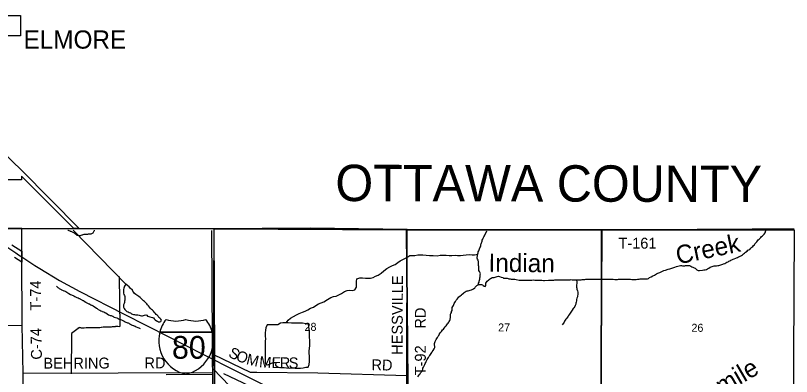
# Model space of a CAD drawing. Extents: x 1588073 to 2013523, y 1090242 to 1357120.
# Drawn here: x 1754621 to 1775971, y 1256594 to 1266514 of the extents above; entities that cross this region are included whole.
import ezdxf

# ---------------------------------------------------------------- set-up
doc = ezdxf.new("R2010")
doc.units = 0
for name, color, linetype in [('GM_X_Adjacent_County', 7, 'Continuous'), ('GM_X_Adjacent_County_Text', 7, 'Continuous'), ('GM_X_Corporation', 7, 'Continuous'), ('GM_X_Corporation_Text', 7, 'Continuous'), ('GM_X_County', 7, 'Continuous'), ('GM_X_County_Road', 7, 'Continuous'), ('GM_X_County_Road_Text', 7, 'Continuous'), ('GM_X_Interstate_Location', 7, 'Continuous'), ('GM_X_Interstate_Route', 7, 'Continuous'), ('GM_X_Interstate_Shield', 7, 'Continuous'), ('GM_X_Minor_Lake', 7, 'Continuous'), ('GM_X_Minor_River', 7, 'Continuous'), ('GM_X_Minor_River_Text', 7, 'Continuous'), ('GM_X_Section', 7, 'Continuous'), ('GM_X_Section_Text', 7, 'Continuous'), ('GM_X_State_Route', 7, 'Continuous'), ('GM_X_Township', 7, 'Continuous'), ('GM_X_Township_Road', 7, 'Continuous'), ('GM_X_Township_Road_Text', 7, 'Continuous')]:
    doc.layers.add(name, color=color, linetype=linetype)

msp = doc.modelspace()

# ---------------------------------------------------------------- linework, layer by layer
at = {"layer": 'GM_X_Adjacent_County'}
msp.add_lwpolyline([(1753720, 1260662), (1754797, 1260665), (1760083, 1260656), (1762727, 1260673), (1765400, 1260637), (1770764, 1260628), (1770979, 1260628), (1771265, 1260627), (1771684, 1260628), (1772128, 1260628), (1772506, 1260627), (1773015, 1260628), (1773375, 1260630), (1773589, 1260631), (1773829, 1260633), (1774262, 1260637), (1774492, 1260637), (1774886, 1260638), (1775116, 1260640), (1775856, 1260641), (1776044, 1260641)], dxfattribs=at)
at = {"layer": 'GM_X_Corporation'}
for points in [[(1753089, 1266514), (1754756, 1266514), (1754759, 1266288), (1754760, 1266162), (1754759, 1266044), (1754757, 1265960), (1754718, 1265961), (1754408, 1265960)], [(1753756, 1263240), (1754783, 1262263), (1756374, 1260663), (1756225, 1260662), (1754784, 1262101), (1754785, 1261998), (1753120, 1261998)], [(1754523, 1260215), (1754793, 1260039), (1754791, 1259878), (1754791, 1259736), (1754595, 1259865)]]:
    msp.add_lwpolyline(points, dxfattribs=at)
at = {"layer": 'GM_X_County'}
msp.add_lwpolyline([(1753720, 1260662), (1754797, 1260665), (1760083, 1260656), (1762727, 1260673), (1765400, 1260637), (1770764, 1260628), (1770979, 1260628), (1771265, 1260627), (1771684, 1260628), (1772128, 1260628), (1772506, 1260627), (1773015, 1260628), (1773375, 1260630), (1773589, 1260631), (1773829, 1260633), (1774262, 1260637), (1774492, 1260637), (1774886, 1260638), (1775116, 1260640), (1775856, 1260641), (1776044, 1260641)], dxfattribs=at)
at = {"layer": 'GM_X_County_Road'}
for points in [[(1760069, 1257196), (1760083, 1260656)], [(1752156, 1257998), (1754803, 1258006)], [(1754829, 1256687), (1754803, 1258006)], [(1759946, 1242582), (1760099, 1247215), (1760179, 1250093), (1760141, 1250222), (1760108, 1252739), (1760060, 1256704), (1760069, 1257059), (1760069, 1257196)], [(1760069, 1257196), (1761079, 1256712), (1761261, 1256710), (1761263, 1256710)], [(1754829, 1256687), (1760060, 1256704)], [(1761263, 1256710), (1762943, 1256691), (1765384, 1256619)], [(1765398, 1255365), (1765384, 1256619)]]:
    msp.add_lwpolyline(points, dxfattribs=at)
at = {"layer": 'GM_X_Interstate_Route'}
for points in [[(1753606, 1260661), (1753766, 1260560), (1754626, 1259989), (1754703, 1259938)], [(1754703, 1259938), (1754791, 1259878), (1755155, 1259642), (1755289, 1259557), (1755835, 1259231), (1756392, 1258927), (1757613, 1258305), (1758839, 1257685), (1759779, 1257207), (1760069, 1257059), (1760393, 1256899), (1761194, 1256491), (1762560, 1255798), (1762986, 1255590), (1763226, 1255479), (1763954, 1255170), (1764295, 1255029), (1765404, 1254577), (1765567, 1254515), (1766890, 1253983), (1769289, 1253012), (1770022, 1252715), (1770708, 1252436)]]:
    msp.add_lwpolyline(points, dxfattribs=at)
at = {"layer": 'GM_X_Interstate_Shield'}
for p, q in [((1758588, 1257808), (1760031, 1257808)), ((1760031, 1257808), (1758588, 1257808)), ((1760031, 1257808), (1758588, 1257808))]:
    msp.add_line(p, q, dxfattribs=at)
for centre, start, end in [((1759497, 1257578), 141.669, 165.8066), ((1759036, 1259056), 253.0091, 286.9909), ((1759584, 1259056), 253.0091, 286.9909), ((1759122, 1257578), 14.1934, 38.331), ((1759497, 1257578), 165.8066, 258.463), ((1759122, 1257578), 281.537, 14.1934)]:
    msp.add_arc(centre, 938, start, end, dxfattribs=at)
at = {"layer": 'GM_X_Minor_Lake'}
for p, q in [((1762712, 1257817), (1762686, 1258028)), ((1762716, 1257438), (1762712, 1257817))]:
    msp.add_line(p, q, dxfattribs=at)
for points in [[(1757656, 1259131), (1757641, 1259105), (1757623, 1259075), (1757612, 1259047), (1757598, 1259020), (1757589, 1258982), (1757591, 1258944), (1757596, 1258911), (1757594, 1258881), (1757603, 1258849), (1757615, 1258821), (1757624, 1258787), (1757632, 1258753), (1757633, 1258723), (1757633, 1258694), (1757623, 1258663), (1757616, 1258631), (1757608, 1258599), (1757595, 1258565), (1757591, 1258533), (1757596, 1258499), (1757608, 1258466), (1757629, 1258436), (1757657, 1258406), (1757688, 1258381), (1757716, 1258367), (1757748, 1258356), (1757780, 1258340), (1757810, 1258315), (1757837, 1258307), (1757865, 1258298), (1757895, 1258294), (1757925, 1258291), (1757955, 1258285), (1757983, 1258284), (1758019, 1258274), (1758053, 1258265), (1758085, 1258259), (1758113, 1258258), (1758145, 1258266), (1758173, 1258278), (1758204, 1258287), (1758236, 1258281), (1758255, 1258252), (1758287, 1258238), (1758315, 1258233), (1758357, 1258221), (1758389, 1258216), (1758417, 1258206), (1758436, 1258176), (1758466, 1258149), (1758502, 1258125), (1758529, 1258110), (1758559, 1258096), (1758589, 1258093), (1758621, 1258107), (1758636, 1258137), (1758618, 1258165), (1758595, 1258193), (1758565, 1258216), (1758543, 1258248), (1758518, 1258279), (1758490, 1258299), (1758463, 1258330), (1758439, 1258358), (1758417, 1258390), (1758390, 1258417), (1758360, 1258433), (1758336, 1258462), (1758309, 1258494), (1758281, 1258531), (1758256, 1258559), (1758230, 1258591), (1758173, 1258650), (1758143, 1258673), (1758112, 1258703), (1758082, 1258736), (1758049, 1258762), (1758017, 1258787), (1757985, 1258810), (1757957, 1258830), (1757928, 1258850), (1757898, 1258877), (1757874, 1258905), (1757851, 1258936), (1757835, 1258964), (1757776, 1259025), (1757750, 1259055)], [(1757750, 1259055), (1757656, 1259131)], [(1762686, 1258028), (1762616, 1258036), (1762518, 1258055), (1762365, 1258056), (1762291, 1258060), (1762215, 1258063), (1762127, 1258069), (1762059, 1258072), (1761977, 1258070), (1761909, 1258059), (1761840, 1258011), (1761772, 1258011), (1761696, 1258016), (1761620, 1258012), (1761548, 1258015), (1761506, 1257933), (1761495, 1257865), (1761487, 1257796), (1761494, 1257702), (1761495, 1257628), (1761493, 1257560), (1761488, 1257479), (1761486, 1257391), (1761489, 1257315), (1761493, 1257233), (1761492, 1257154), (1761488, 1257072), (1761487, 1257004), (1761495, 1256934), (1761567, 1256915), (1761641, 1256949), (1761711, 1256981), (1761783, 1256974), (1761773, 1256906), (1761847, 1256849), (1761935, 1256841), (1762013, 1256836), (1762081, 1256832), (1762149, 1256825), (1762231, 1256827), (1762317, 1256826), (1762387, 1256824), (1762461, 1256825), (1762535, 1256835), (1762606, 1256847), (1762676, 1256846), (1762704, 1256926), (1762707, 1257006), (1762713, 1257079), (1762706, 1257161), (1762702, 1257229), (1762703, 1257297), (1762716, 1257438)]]:
    msp.add_lwpolyline(points, dxfattribs=at)
at = {"layer": 'GM_X_Minor_River'}
for p, q in [((1756209, 1260617), (1757655, 1259130)), ((1760016, 1260606), (1760042, 1255883)), ((1757470, 1259342), (1757494, 1257969)), ((1756160, 1257778), (1756155, 1256670)), ((1756380, 1257939), (1756160, 1257778)), ((1756160, 1257778), (1756160, 1257778)), ((1756326, 1257926), (1756326, 1257928)), ((1760050, 1256809), (1762754, 1254048)), ((1760342, 1256676), (1762756, 1255544)), ((1760038, 1256649), (1758762, 1256638))]:
    msp.add_line(p, q, dxfattribs=at)
for points in [[(1756059, 1260617), (1756072, 1260613), (1756086, 1260605), (1756113, 1260593), (1756127, 1260588), (1756147, 1260586), (1756165, 1260582), (1756181, 1260572), (1756199, 1260559), (1756213, 1260547), (1756231, 1260539), (1756249, 1260527), (1756262, 1260514), (1756280, 1260502), (1756298, 1260488), (1756312, 1260480), (1756332, 1260473), (1756350, 1260469), (1756368, 1260471), (1756386, 1260468), (1756408, 1260470), (1756430, 1260474), (1756452, 1260483), (1756466, 1260489), (1756486, 1260499), (1756507, 1260501), (1756525, 1260502), (1756539, 1260504), (1756559, 1260506), (1756591, 1260506), (1756611, 1260509), (1756629, 1260511), (1756647, 1260515), (1756663, 1260516), (1756681, 1260516), (1756703, 1260518), (1756719, 1260522), (1756735, 1260531), (1756753, 1260545), (1756770, 1260563), (1756780, 1260577), (1756786, 1260593), (1756790, 1260607), (1756793, 1260613)], [(1766694, 1258596), (1766712, 1258630), (1766723, 1258654), (1766747, 1258690), (1766769, 1258720), (1766801, 1258758), (1766822, 1258782), (1766846, 1258802), (1766892, 1258834), (1766914, 1258856), (1766946, 1258879), (1766967, 1258901), (1766997, 1258921), (1767021, 1258935), (1767049, 1258945), (1767075, 1258949), (1767107, 1258955), (1767131, 1258965), (1767163, 1258972), (1767203, 1258996), (1767226, 1259006), (1767254, 1259026), (1767266, 1259048), (1767290, 1259066), (1767318, 1259090), (1767346, 1259112), (1767361, 1259136), (1767363, 1259158), (1767377, 1259188), (1767381, 1259212), (1767387, 1259240), (1767392, 1259266), (1767400, 1259308), (1767404, 1259336), (1767408, 1259358), (1767408, 1259392), (1767413, 1259414), (1767403, 1259442), (1767383, 1259478), (1767373, 1259505), (1767371, 1259563), (1767370, 1259589), (1767366, 1259617), (1767360, 1259645), (1767358, 1259673), (1767361, 1259725), (1767357, 1259749), (1767349, 1259786), (1767335, 1259816), (1767327, 1259842), (1767327, 1259868), (1767330, 1259910), (1767334, 1259938), (1767340, 1259962), (1767348, 1259996), (1767354, 1260020), (1767365, 1260044), (1767375, 1260072), (1767385, 1260098), (1767395, 1260126), (1767411, 1260160), (1767420, 1260186), (1767428, 1260218), (1767436, 1260242), (1767440, 1260267), (1767450, 1260289), (1767457, 1260315), (1767463, 1260339), (1767479, 1260365), (1767491, 1260393), (1767509, 1260429), (1767526, 1260457), (1767589, 1260600)], [(1774993, 1260271), (1775015, 1260293), (1775036, 1260319), (1775058, 1260345), (1775080, 1260365), (1775106, 1260391), (1775126, 1260415), (1775145, 1260439), (1775173, 1260458), (1775193, 1260480), (1775221, 1260508), (1775247, 1260542), (1775262, 1260605)], [(1771701, 1259263), (1771733, 1259264), (1771777, 1259268), (1771811, 1259274), (1771849, 1259274), (1771879, 1259278), (1771913, 1259277), (1771953, 1259279), (1771981, 1259279), (1772013, 1259281), (1772039, 1259289), (1772061, 1259311), (1772110, 1259334), (1772158, 1259356), (1772200, 1259374), (1772232, 1259394), (1772258, 1259412), (1772294, 1259429), (1772325, 1259441), (1772349, 1259455), (1772371, 1259463), (1772425, 1259487), (1772455, 1259505), (1772509, 1259518), (1772582, 1259546), (1772620, 1259554), (1772650, 1259562), (1772678, 1259567), (1772702, 1259575), (1772760, 1259599), (1772808, 1259619), (1772840, 1259625), (1772883, 1259636), (1772913, 1259640), (1772943, 1259640), (1772969, 1259638), (1772997, 1259638), (1773035, 1259639), (1773057, 1259641), (1773111, 1259645), (1773137, 1259645), (1773161, 1259643), (1773201, 1259626), (1773233, 1259608), (1773255, 1259596), (1773289, 1259584), (1773317, 1259571), (1773352, 1259547), (1773366, 1259525), (1773406, 1259509), (1773442, 1259506), (1773520, 1259516), (1773557, 1259522), (1773595, 1259528), (1773631, 1259531), (1773657, 1259553), (1773699, 1259569), (1773737, 1259597), (1773787, 1259613), (1773820, 1259626), (1773848, 1259630), (1773880, 1259634), (1773904, 1259636), (1773940, 1259640), (1773976, 1259646), (1773998, 1259649), (1774054, 1259669), (1774078, 1259679), (1774104, 1259685), (1774134, 1259703), (1774165, 1259713), (1774191, 1259732), (1774225, 1259746), (1774249, 1259764), (1774271, 1259772), (1774303, 1259788), (1774347, 1259808), (1774370, 1259822), (1774396, 1259829), (1774436, 1259845), (1774462, 1259853), (1774490, 1259865), (1774516, 1259881), (1774538, 1259889), (1774562, 1259901), (1774592, 1259920), (1774627, 1259940), (1774651, 1259962), (1774679, 1259980), (1774707, 1260008), (1774749, 1260040), (1774772, 1260062), (1774796, 1260072), (1774822, 1260086), (1774854, 1260119), (1774884, 1260143), (1774908, 1260167), (1774929, 1260189), (1774951, 1260215), (1774963, 1260237), (1774993, 1260271)], [(1762071, 1258071), (1762120, 1258138), (1762190, 1258193), (1762267, 1258243), (1762349, 1258289), (1762429, 1258322), (1762514, 1258358), (1762586, 1258391), (1762660, 1258427), (1762739, 1258469), (1762815, 1258502), (1762883, 1258544), (1762960, 1258594), (1763030, 1258619), (1763106, 1258645), (1763207, 1258710), (1763297, 1258766), (1763367, 1258790), (1763444, 1258805), (1763516, 1258835), (1763586, 1258873), (1763673, 1258930), (1763747, 1258960), (1763815, 1258963), (1763883, 1258961), (1763953, 1258977), (1764002, 1259048), (1764001, 1259133), (1764001, 1259203), (1764014, 1259275), (1764094, 1259301), (1764164, 1259302), (1764246, 1259300), (1764386, 1259295), (1764460, 1259312), (1764529, 1259354), (1764601, 1259380), (1764677, 1259431), (1764758, 1259499), (1764834, 1259557), (1764923, 1259608), (1764991, 1259640), (1765067, 1259672), (1765138, 1259729), (1765206, 1259771), (1765293, 1259815), (1765385, 1259864), (1765466, 1259916), (1765538, 1259921), (1765606, 1259921), (1765688, 1259933), (1765762, 1259936), (1765832, 1259938), (1765920, 1259931), (1766014, 1259920), (1766114, 1259916), (1766218, 1259913), (1766301, 1259927), (1766369, 1259926), (1766471, 1259924), (1766555, 1259923), (1766627, 1259921), (1766717, 1259924), (1766785, 1259922), (1766861, 1259921), (1766941, 1259929), (1767022, 1259934), (1767108, 1259944), (1767184, 1259937), (1767252, 1259937), (1767339, 1259957)], [(1767355, 1259125), (1767397, 1259121), (1767443, 1259121), (1767467, 1259115), (1767490, 1259091), (1767514, 1259072), (1767542, 1259068), (1767557, 1259096), (1767561, 1259134), (1767565, 1259158), (1767575, 1259184), (1767599, 1259212), (1767640, 1259248), (1767662, 1259264), (1767686, 1259282), (1767710, 1259296), (1767734, 1259310), (1767758, 1259314), (1767790, 1259315), (1767818, 1259321), (1767849, 1259335), (1767873, 1259343), (1767909, 1259347), (1767933, 1259345), (1767983, 1259326), (1768025, 1259310), (1768049, 1259298), (1768085, 1259294), (1768117, 1259297), (1768147, 1259293), (1768173, 1259287), (1768195, 1259281), (1768227, 1259273), (1768259, 1259270), (1768309, 1259270), (1768331, 1259272), (1768359, 1259270), (1768393, 1259255), (1768477, 1259237), (1768519, 1259237), (1768585, 1259240), (1768613, 1259238), (1768651, 1259240), (1768673, 1259242), (1768719, 1259241), (1768745, 1259243), (1768773, 1259243), (1768829, 1259245), (1768869, 1259246), (1768911, 1259244), (1768957, 1259242), (1769005, 1259242), (1769101, 1259237), (1769145, 1259235), (1769175, 1259234), (1769282, 1259236), (1769314, 1259238), (1769428, 1259245), (1769458, 1259247), (1769540, 1259252), (1769584, 1259254), (1769730, 1259253), (1769758, 1259251), (1769794, 1259253), (1769854, 1259252), (1769878, 1259254), (1769910, 1259256), (1769940, 1259254), (1769971, 1259252), (1770007, 1259247), (1770081, 1259247), (1770135, 1259250), (1770185, 1259252), (1770211, 1259256), (1770281, 1259262), (1770313, 1259265), (1770341, 1259267), (1770375, 1259269), (1770489, 1259268), (1770521, 1259268), (1770627, 1259267), (1770649, 1259265), (1770756, 1259265), (1770802, 1259266), (1770852, 1259270), (1770948, 1259269), (1770976, 1259269), (1771022, 1259267), (1771066, 1259265), (1771114, 1259262), (1771182, 1259262), (1771214, 1259264), (1771270, 1259265), (1771296, 1259265), (1771346, 1259267), (1771490, 1259266), (1771546, 1259264), (1771580, 1259263), (1771605, 1259261), (1771677, 1259263), (1771701, 1259263)], [(1770053, 1259247), (1770064, 1259185), (1770062, 1259153), (1770054, 1259115), (1770054, 1259091), (1770057, 1259052), (1770063, 1259020), (1770069, 1258990), (1770081, 1258946), (1770092, 1258910), (1770092, 1258846), (1770086, 1258807), (1770080, 1258785), (1770069, 1258749), (1770059, 1258709), (1770053, 1258675), (1770048, 1258637), (1770042, 1258609), (1770038, 1258585), (1770022, 1258545), (1770006, 1258519), (1769983, 1258483), (1769965, 1258461), (1769941, 1258415), (1769921, 1258391), (1769900, 1258365), (1769880, 1258337), (1769862, 1258305), (1769834, 1258269), (1769824, 1258247), (1769807, 1258219), (1769783, 1258191), (1769763, 1258164), (1769747, 1258138), (1769729, 1258112), (1769716, 1258086), (1769696, 1258062), (1769660, 1258014)], [(1755750, 1259077), (1755786, 1259040), (1755802, 1259030), (1755818, 1259012), (1755837, 1259004), (1755859, 1258993), (1755873, 1258985), (1755889, 1258977), (1755911, 1258966), (1755949, 1258950), (1755963, 1258946), (1755985, 1258935), (1756001, 1258929), (1756030, 1258907), (1756058, 1258894), (1756072, 1258886), (1756090, 1258876), (1756132, 1258851), (1756159, 1258838), (1756183, 1258828), (1756205, 1258816), (1756227, 1258807), (1756251, 1258793), (1756275, 1258781), (1756293, 1258770), (1756310, 1258762), (1756344, 1258752), (1756368, 1258739), (1756384, 1258733), (1756398, 1258731), (1756412, 1258721), (1756426, 1258712), (1756444, 1258700), (1756459, 1258688), (1756475, 1258683), (1756493, 1258679), (1756505, 1258663), (1756551, 1258636), (1756565, 1258624), (1756605, 1258609), (1756622, 1258597), (1756638, 1258593), (1756652, 1258591), (1756668, 1258582), (1756690, 1258566), (1756710, 1258556), (1756724, 1258552), (1756740, 1258545), (1756760, 1258533), (1756797, 1258504), (1756815, 1258494), (1756847, 1258470), (1756865, 1258459), (1756896, 1258437), (1756940, 1258414), (1756966, 1258396), (1756994, 1258387), (1757008, 1258383), (1757039, 1258371), (1757055, 1258366), (1757079, 1258352), (1757107, 1258341), (1757143, 1258319), (1757178, 1258292), (1757208, 1258274), (1757224, 1258268), (1757238, 1258267), (1757254, 1258265), (1757268, 1258259), (1757286, 1258255), (1757304, 1258248), (1757316, 1258234), (1757338, 1258222), (1757411, 1258201), (1757449, 1258186), (1757475, 1258172), (1757491, 1258165), (1757541, 1258149), (1757555, 1258140), (1757594, 1258124), (1757614, 1258110), (1757642, 1258095), (1757656, 1258089), (1757680, 1258079), (1757706, 1258066), (1757720, 1258064), (1757734, 1258058), (1757759, 1258039), (1757781, 1258033), (1757813, 1258014), (1757829, 1258006), (1757857, 1257994), (1757871, 1257990), (1757887, 1257983), (1757911, 1257975), (1757942, 1257958), (1757986, 1257944), (1758010, 1257931), (1758028, 1257925), (1758048, 1257915)], [(1765694, 1256586), (1765710, 1256614), (1765728, 1256638), (1765750, 1256666), (1765766, 1256690), (1765789, 1256718), (1765815, 1256760), (1765825, 1256794), (1765829, 1256818), (1765848, 1256848), (1765874, 1256902), (1765882, 1256926), (1765894, 1256950), (1765908, 1256980), (1765921, 1257004), (1765939, 1257040), (1765949, 1257062), (1765963, 1257088), (1765981, 1257116), (1766006, 1257150), (1766018, 1257174), (1766054, 1257222), (1766074, 1257248), (1766085, 1257270), (1766109, 1257308), (1766137, 1257354), (1766156, 1257394), (1766156, 1257424), (1766150, 1257448), (1766150, 1257472), (1766152, 1257498), (1766158, 1257526), (1766171, 1257552), (1766197, 1257606), (1766215, 1257638), (1766229, 1257662), (1766250, 1257698), (1766264, 1257722), (1766280, 1257748), (1766306, 1257792), (1766337, 1257830), (1766369, 1257872), (1766395, 1257898), (1766411, 1257920), (1766446, 1257956), (1766468, 1257984), (1766488, 1258010), (1766510, 1258038), (1766526, 1258060), (1766541, 1258086), (1766555, 1258108), (1766571, 1258136), (1766579, 1258160), (1766581, 1258184), (1766585, 1258208), (1766590, 1258230), (1766588, 1258268), (1766592, 1258304), (1766600, 1258326), (1766612, 1258354), (1766619, 1258382), (1766631, 1258410), (1766637, 1258432), (1766637, 1258462), (1766639, 1258486), (1766668, 1258548), (1766678, 1258574), (1766694, 1258596)], [(1756382, 1257941), (1756392, 1257939), (1756408, 1257937), (1756428, 1257931), (1756444, 1257930), (1756480, 1257926), (1756494, 1257928), (1756512, 1257929), (1756560, 1257935), (1756593, 1257942), (1756647, 1257941), (1756675, 1257939), (1756695, 1257937), (1756731, 1257938), (1756769, 1257942), (1756799, 1257943), (1756865, 1257942), (1756899, 1257940), (1756929, 1257937), (1756943, 1257937), (1756973, 1257947), (1756989, 1257946), (1757031, 1257954), (1757063, 1257955), (1757107, 1257957), (1757123, 1257956), (1757153, 1257958), (1757177, 1257958), (1757193, 1257955), (1757214, 1257957), (1757230, 1257959), (1757264, 1257958), (1757286, 1257964), (1757302, 1257966), (1757332, 1257967), (1757368, 1257971), (1757382, 1257973), (1757414, 1257976), (1757436, 1257974), (1757494, 1257969)]]:
    msp.add_lwpolyline(points, dxfattribs=at)
at = {"layer": 'GM_X_Section'}
for points in [[(1765376, 1260623), (1765421, 1255368), (1760110, 1255379), (1760083, 1260650)], [(1770748, 1260624), (1770734, 1255374), (1765421, 1255368), (1765376, 1260623)], [(1776049, 1260626), (1776017, 1255360), (1770734, 1255374), (1770748, 1260624)]]:
    msp.add_lwpolyline(points, close=True, dxfattribs=at)
at = {"layer": 'GM_X_State_Route'}
msp.add_lwpolyline([(1770708, 1252436), (1770730, 1255350), (1770764, 1260628)], dxfattribs=at)
at = {"layer": 'GM_X_Township'}
msp.add_lwpolyline([(1776044, 1260641), (1775856, 1260641), (1775116, 1260640), (1774886, 1260638), (1774492, 1260637), (1774262, 1260637), (1773829, 1260633), (1773589, 1260631), (1773375, 1260630), (1773015, 1260628), (1772506, 1260627), (1772128, 1260628), (1771684, 1260628), (1771265, 1260627), (1770979, 1260628), (1770764, 1260628), (1765400, 1260637), (1762727, 1260673), (1760083, 1260656), (1754797, 1260665), (1753720, 1260662)], dxfattribs=at)
at = {"layer": 'GM_X_Township_Road'}
for points in [[(1754803, 1258006), (1754791, 1259878), (1754797, 1260665)], [(1765384, 1256619), (1765400, 1260637)], [(1770764, 1260628), (1770979, 1260628), (1771265, 1260627), (1771684, 1260628), (1772128, 1260628), (1772506, 1260627), (1773015, 1260628), (1773375, 1260630), (1773589, 1260631), (1773829, 1260633), (1774262, 1260637), (1774492, 1260637), (1774886, 1260638), (1775116, 1260640), (1775856, 1260641), (1776044, 1260641)], [(1754713, 1245496), (1754762, 1247008), (1754809, 1248357), (1754854, 1250091), (1754808, 1250304), (1754813, 1250637), (1754814, 1252237), (1754817, 1252759), (1754829, 1256687)]]:
    msp.add_lwpolyline(points, dxfattribs=at)

# ---------------------------------------------------------------- texts
at = {"layer": 'GM_X_Adjacent_County_Text'}
msp.add_text('OTTAWA COUNTY', height=1000, rotation=359.8588, dxfattribs=at).set_placement((1763421, 1261415))
at = {"layer": 'GM_X_Corporation_Text'}
msp.add_text('ELMORE', height=500, rotation=0, dxfattribs=at).set_placement((1754842, 1265605))
at = {"layer": 'GM_X_County_Road_Text'}
for s, rotation, p in [('C-74', 91.3713, (1755350, 1257059)), ('S', 333.8749, (1760456, 1257147)), ('BEHRING', 0.1554, (1755387, 1256808)), ('RD', 0, (1758168, 1256816)), ('O', 338.1307, (1760660, 1257048)), ('M', 346.6423, (1760952, 1256935)), ('M', 355.1539, (1761316, 1256852)), ('E', 359.4097, (1761665, 1256824)), ('R', 359.4097, (1761890, 1256821)), ('S', 359.4097, (1762136, 1256819)), ('RD', 358.5194, (1764410, 1256768))]:
    msp.add_text(s, height=300, rotation=rotation, dxfattribs=at).set_placement(p)
at = {"layer": 'GM_X_Interstate_Location'}
for s in ['.', '-', ',']:
    msp.add_text(s, height=1, dxfattribs=at).set_placement((1759310, 1257409))
msp.add_text('80', height=1, rotation=0, dxfattribs=at).set_placement((1759105, 1257202))
at = {"layer": 'GM_X_Interstate_Shield'}
msp.add_text('80', height=625, dxfattribs=at).set_placement((1758925, 1257081))
at = {"layer": 'GM_X_Minor_River_Text'}
for s, rotation, p in [('Creek', 11.6416, (1772845, 1259672)), ('Indian', 359.5057, (1767634, 1259472)), ('Ninemile', 30.1524, (1772868, 1255384))]:
    msp.add_text(s, height=500.3, rotation=rotation, dxfattribs=at).set_placement(p)
at = {"layer": 'GM_X_Section_Text'}
for s, p in [('28', (1762573, 1257847)), ('27', (1767899, 1257830)), ('26', (1773218, 1257821))]:
    msp.add_text(s, height=221, rotation=0, dxfattribs=at).set_placement(p)
at = {"layer": 'GM_X_Township_Road_Text'}
for s, rotation, p in [('T-161', 359.9428, (1771209, 1260107)), ('HESSVILLE', 89.742, (1765270, 1257187)), ('T-74', 90.3656, (1755325, 1258408)), ('RD', 90, (1765909, 1257909)), ('T-92', 90, (1765909, 1256624))]:
    msp.add_text(s, height=300, rotation=rotation, dxfattribs=at).set_placement(p)

doc.saveas('drawing.dxf')
